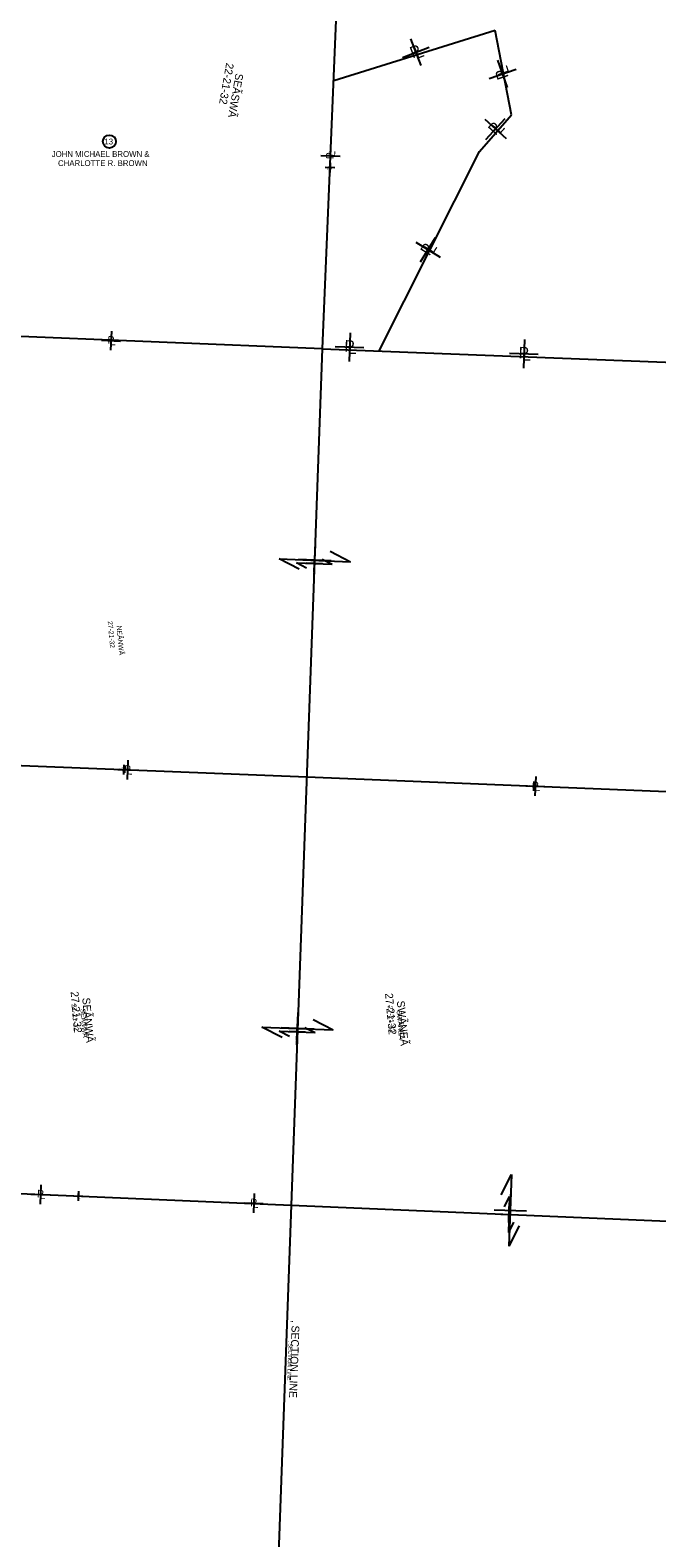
# Model space of a CAD drawing. Extents: x 2814293 to 2835768, y 121185 to 156337.
# Drawn here: x 2822390 to 2824318, y 127276 to 131914 of the extents above; entities that cross this region are included whole.
import ezdxf

# ---------------------------------------------------------------- set-up
doc = ezdxf.new("R2010")
doc.units = 0
for name, color, linetype in [('Photo-Retaining wall', 7, 'Continuous'), ('Roadway-Alignment notes', 7, 'Continuous'), ('Roadway-Ditches', 7, 'Continuous'), ('Roadway-Edge of pavement', 7, 'Continuous'), ('Roadway-Edge of shoulder', 7, 'Continuous'), ('Roadway-Entrances', 7, 'Continuous'), ('Roadway-Safety', 7, 'Continuous'), ('Roadway-Walls', 7, 'Continuous'), ('Scratch-2', 7, 'Continuous'), ('Scratch-5', 7, 'Continuous')]:
    doc.layers.add(name, color=color, linetype=linetype)

msp = doc.modelspace()

# ---------------------------------------------------------------- linework, layer by layer
at = {"layer": 'Roadway-Ditches'}
msp.add_circle((2822634.1, 131571.7), 20, dxfattribs=at)
at = {"layer": 'Roadway-Edge of pavement'}
for p, q in [((2823263.7, 130248.1), (2823265.6, 130298.1)), ((2823209.7, 130275.2), (2823319.6, 130271)), ((2823240.8, 130259.2), (2823209.7, 130275.2)), ((2823289.6, 130272.1), (2823239.7, 130274.1)), ((2823264.6, 130273.1), (2823264.6, 130273.1)), ((2823288.5, 130287), (2823319.6, 130271)), ((2823156.6, 128834.5), (2823266.6, 128830.3)), ((2823187.8, 128818.5), (2823156.6, 128834.5)), ((2823236.6, 128831.4), (2823186.6, 128833.4)), ((2823210.6, 128807.4), (2823212.6, 128857.4)), ((2823211.6, 128832.4), (2823211.6, 128832.4)), ((2823235.4, 128846.3), (2823266.6, 128830.3)), ((2823849.3, 128294.4), (2823865.2, 128325.6)), ((2823865.2, 128325.6), (2823861.3, 128215.7)), ((2823838.2, 128271.5), (2823888.2, 128269.8)), ((2823862.4, 128245.7), (2823864.1, 128295.6)), ((2823863.2, 128270.6), (2823863.2, 128270.6)), ((2823877.2, 128246.9), (2823861.3, 128215.7))]:
    msp.add_line(p, q, dxfattribs=at)
at = {"layer": 'Roadway-Edge of shoulder'}
for p, q in [((2823560.6, 131887.7), (2823592.4, 131805.2)), ((2823535.2, 131830.5), (2823617.7, 131862.3)), ((2823802, 131765.5), (2823885.4, 131794.5)), ((2823858.2, 131738.2), (2823829.2, 131821.7)), ((2823792.1, 131577.7), (2823851.6, 131643)), ((2823789.2, 131640.1), (2823854.5, 131580.6)), ((2823313.3, 131498.7), (2823315.4, 131557.6)), ((2823284.9, 131529.2), (2823343.8, 131527.2)), ((2823590.8, 131201.6), (2823637.4, 131276.7)), ((2823576.6, 131262.5), (2823651.7, 131215.8)), ((2822609.5, 130960.2), (2822668.4, 130958)), ((2822640.1, 130988.5), (2822637.8, 130929.7)), ((2823374.4, 130983.6), (2823371.3, 130895.3)), ((2823910.6, 130963), (2823907.5, 130874.7)), ((2823328.7, 130941), (2823417, 130937.9)), ((2823864.8, 130920.4), (2823953.2, 130917.3)), ((2822690.9, 129668), (2822688.7, 129609.1)), ((2822660.4, 129639.7), (2822719.2, 129637.4)), ((2823945.4, 129617.9), (2823943.1, 129559)), ((2823914.8, 129589.6), (2823973.7, 129587.3)), ((2822423.3, 128361.7), (2822421, 128302.9)), ((2822392.7, 128333.5), (2822451.6, 128331.2)), ((2823048.5, 128306.5), (2823107.3, 128304.3)), ((2823079, 128334.8), (2823076.8, 128276))]:
    msp.add_line(p, q, dxfattribs=at)
at = {"layer": 'Roadway-Entrances'}
for p, q in [((2823399.5, 133588.1), (2823288.6, 130934)), ((2823820.4, 131913), (2823324, 131758.3)), ((2823871.2, 131654.3), (2823820.4, 131913)), ((2823772.4, 131541.5), (2823871.2, 131654.3)), ((2823463.4, 130927.3), (2823772.4, 131541.5)), ((2823288.6, 130934), (2820645.7, 131042.3)), ((2823288.6, 130934), (2823193.2, 128299.4)), ((2823288.6, 130934), (2825955.3, 130831.3)), ((2821914.4, 129670.7), (2823240.9, 129616.7)), ((2823240.9, 129616.7), (2825907.1, 129508.7)), ((2820536.2, 128412.4), (2823193.2, 128299.4)), ((2823193.2, 128299.4), (2823097.9, 125665)), ((2823193.2, 128299.4), (2825858.9, 128186.1))]:
    msp.add_line(p, q, dxfattribs=at)
at = {"layer": 'Roadway-Walls'}
for p, q in [((2823313, 131505.8), (2823312, 131476.3)), ((2823327.2, 131490.5), (2823297.8, 131491.6)), ((2822678.4, 129624.4), (2822679.5, 129653.8)), ((2822693.6, 129638.5), (2822664.2, 129639.7)), ((2823940.1, 129603.2), (2823939, 129573.8)), ((2823924.8, 129589.1), (2823954.2, 129588)), ((2822523.4, 128328.3), (2822552.8, 128327.2)), ((2822538.7, 128342.4), (2822537.5, 128313))]:
    msp.add_line(p, q, dxfattribs=at)
at = {"layer": 'Scratch-2'}
for p, q in [((2823264, 130233.4), (2823267.9, 130333.3)), ((2823313.6, 130311.1), (2823375.8, 130279.1)), ((2823156, 130287.6), (2823375.8, 130279.1)), ((2823218.2, 130255.6), (2823156, 130287.6)), ((2823315.9, 130281.4), (2823216, 130285.3)), ((2823265.9, 130283.3), (2823265.9, 130283.3)), ((2823210.9, 128792.7), (2823214.8, 128892.6)), ((2823260.6, 128870.4), (2823322.8, 128838.4)), ((2823103, 128846.9), (2823322.8, 128838.4)), ((2823165.2, 128814.9), (2823103, 128846.9)), ((2823262.8, 128840.7), (2823162.9, 128844.6)), ((2823212.9, 128842.7), (2823212.9, 128842.7)), ((2823839.2, 128331.1), (2823871, 128393.5)), ((2823871, 128393.5), (2823863.2, 128173.6)), ((2823865.3, 128233.6), (2823868.8, 128333.5)), ((2823817.1, 128285.3), (2823917.1, 128281.8)), ((2823867.1, 128283.5), (2823867.1, 128283.5)), ((2823895, 128235.9), (2823863.2, 128173.6))]:
    msp.add_line(p, q, dxfattribs=at)

# ---------------------------------------------------------------- texts
at = {"layer": 'Photo-Retaining wall'}
for s, p in [('27-21-32', (2822628.9, 130095.6)), ('NEÃNWÃ', (2822656.3, 130081.4)), ('27-21-32', (2822517.4, 128917.9)), ('27-21-32', (2823490.1, 128912.1)), ('SEÃNWÃ', (2822544.7, 128903.7)), ('SWÃNEÃ', (2823517.4, 128897.9))]:
    msp.add_text(s, height=15, rotation=275.0693, dxfattribs=at).set_placement(p)
at = {"layer": 'Roadway-Alignment notes'}
for s, rotation, p in [('22-21-32', 260.038, (2822993.6, 131814.8)), ('SEÃSWÃ', 260.038, (2823022.5, 131782.8)), ('27-21-32', 275.0693, (2822514.8, 128956.1)), ('SEÃNWÃ', 275.0693, (2822550.6, 128936.7)), ('27-21-32', 275.0693, (2823482, 128950.8)), ('SWÃNEÃ', 275.0693, (2823518.2, 128927.4))]:
    msp.add_text(s, height=24, rotation=rotation, dxfattribs=at).set_placement(p)
at = {"layer": 'Roadway-Ditches'}
for s, p in [('13', (2822618.6, 131562.7)), ('JOHN MICHAEL BROWN &', (2822456.6, 131524.2)), ('CHARLOTTE R. BROWN', (2822476, 131496.2))]:
    msp.add_text(s, height=18, rotation=0.038, dxfattribs=at).set_placement(p)
at = {"layer": 'Roadway-Edge of shoulder'}
for s, height, rotation, p in [('P', 35.3, 21.0527, (2823566.7, 131827.2)), ('L', 35.3, 21.0527, (2823580.2, 131825.5)), ('P', 35.3, 109.1457, (2823862.6, 131769.6)), ('L', 35.3, 109.1457, (2823864.8, 131783)), ('P', 35.3, 47.6691, (2823821.7, 131588.8)), ('L', 35.3, 47.6691, (2823834.6, 131593.3)), ('P', 23.6, 87.9775, (2823323.6, 131517.2)), ('L', 23.6, 87.9775, (2823328.2, 131525)), ('P', 35.3, 58.1586, (2823618, 131217.9)), ('L', 35.3, 58.1586, (2823629.8, 131224.7)), ('P', 23.6, 357.7804, (2822627.9, 130949.9)), ('L', 23.6, 357.7804, (2822635.8, 130945.3)), ('P', 35.3, 357.9773, (2823356.4, 130925.6)), ('L', 35.3, 357.9773, (2823368.1, 130918.7)), ('P', 35.3, 357.9773, (2823892.5, 130905)), ('L', 35.3, 357.9773, (2823904.3, 130898.1)), ('P', 23.6, 357.7804, (2822678.8, 129629.4)), ('L', 23.6, 357.7804, (2822686.6, 129624.7)), ('P', 23.6, 357.7804, (2823933.2, 129579.2)), ('L', 23.6, 357.7804, (2823941, 129574.6)), ('P', 23.6, 357.7804, (2822411.1, 128323.1)), ('L', 23.6, 357.7804, (2822418.9, 128318.5)), ('P', 23.6, 357.7804, (2823066.8, 128296.2)), ('L', 23.6, 357.7804, (2823074.7, 128291.6))]:
    msp.add_text(s, height=height, rotation=rotation, dxfattribs=at).set_placement(p)
at = {"layer": 'Roadway-Safety'}
msp.add_text('‚ SECTION LINE', height=12, rotation=267.9775, dxfattribs=at).set_placement((2823185.2, 127882.9))
at = {"layer": 'Roadway-Walls'}
for s, rotation, p in [('L', 267.9775, (2823305.6, 131492.6)), ('P', 267.9775, (2823307.9, 131496.5)), ('L', 177.7804, (2822680.5, 129646)), ('P', 177.7804, (2822684.4, 129643.7)), ('P', 357.7804, (2823934, 129583.9)), ('L', 357.7804, (2823937.9, 129581.6)), ('P', 357.7804, (2822532.6, 128323.1)), ('L', 357.7804, (2822536.5, 128320.8))]:
    msp.add_text(s, height=11.8, rotation=rotation, dxfattribs=at).set_placement(p)
at = {"layer": 'Scratch-5'}
msp.add_text('‚ SECTION LINE', height=24, rotation=267.9775, dxfattribs=at).set_placement((2823195.2, 127945.5))

doc.saveas('drawing.dxf')
